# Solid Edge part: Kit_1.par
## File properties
Dokumentum tartalom típus: 0
Last saved by: psaghy
Revision: 78
Sűrűség: 0,000 kg/m^3
Pontosság: 0,990
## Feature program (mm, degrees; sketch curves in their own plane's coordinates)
base feature "unnamed BaseFeature 1"
thread "unnamed Thread 1"
chamfer "unnamed Chamfer 1"
sketch for "Furat_2" plane through (0, -41.625, 7) normal (0, 0, 1) x-axis (0, 1, 0)
  hole centre (0.625, 0) bore radius 5
hole "Furat_2" diameter 10 through
sketch for "Furat_3" plane through (0, -41.625, 7) normal (0, 0, 1) x-axis (0, 1, 0)
  hole centre (0.625, 0) bore radius 2.067
hole "Furat_3" nominal diameter 5 finite  ThreadDepth = 4.5 mm
chamfer "Letörés_2" setback 0.5
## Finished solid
Body 1: solid body, 50 faces, 55 edges, 8 vertices.
  Faces by surface: cylinder 16, plane 16, cone 11, torus 7
  Edges by curve: circle 47, line 6, intersection 2
Bounding box of the edges (mm; curved faces can reach further): 16.000 x 22.250 x 15.000, from (-8, -58, -8) to (8, -35.75, 7).
Cylindrical faces by radius (mm): R2.067 x2, R2.15 x2, R2.213 x1, R2.35 x1, R3.25 x1, R3.3 x1, R3.35 x1, R4.05 x1, R4.1 x1, R5.6 x2, R6 x2, R8 x1
Conical faces (half-angle, radius in mm at the cone's reference point): 5.7574 deg R3.25 x1, 12.9869 deg R2.0077 x1, 14.7799 deg R2.7245 x1, 15 deg R4.05 x1, 16.6443 deg R2.35 x1, 20.502 deg R2.513 x1, 45 deg R2.067 x1, 45 deg R3.4 x1, 45 deg R3.5 x1, 45 deg R6 x1, 60 deg R5.5 x1
Toroidal faces (ring radius, tube radius in mm): R2.2 r0.2 x1, R2.3 r0.3 x1, R2.9179 r0.2 x1, R3.1 r0.2 x1, R3.85 r0.2 x1, R4.09 r0.01 x2
Planar faces by outward normal: +y 5, +z 2, -y 9
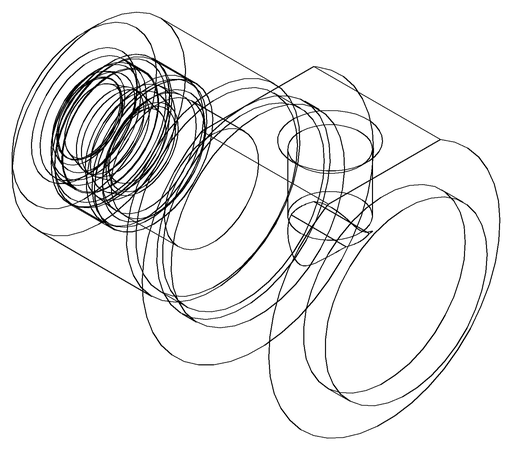
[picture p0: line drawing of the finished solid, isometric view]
